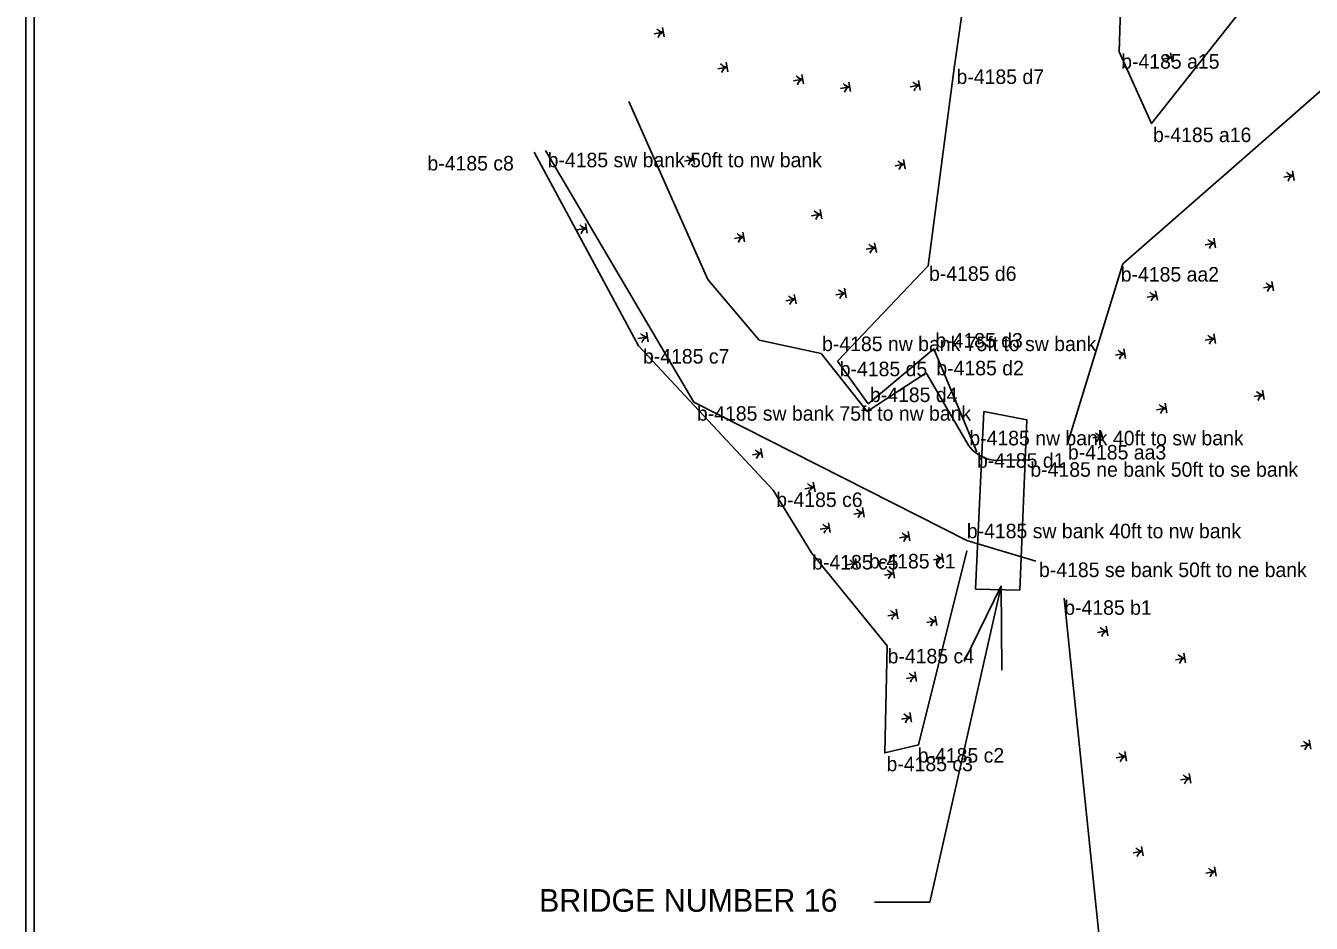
# Model space of a CAD drawing. Extents: x 2598976 to 2600165, y 728604 to 730243.
# Drawn here: x 2598981 to 2599645, y 729053 to 729516 of the extents above; entities that cross this region are included whole.
import ezdxf

# ---------------------------------------------------------------- set-up
doc = ezdxf.new("R2010")
doc.units = 0
for name, color, linetype in [('Old_Level_24', 7, 'Continuous'), ('Old_Level_3', 7, 'Continuous'), ('Old_Level_53', 7, 'Continuous'), ('Old_Level_57', 7, 'Continuous'), ('Old_Level_62', 7, 'Continuous'), ('Old_Level_63', 7, 'Continuous')]:
    doc.layers.add(name, color=color, linetype=linetype)

msp = doc.modelspace()

# ---------------------------------------------------------------- linework, layer by layer
at = {"layer": 'Old_Level_24'}
for q in [(2599465.37, 729187.6), (2599484.79, 729183.19)]:
    msp.add_line((2599484.45, 729226.71), q, dxfattribs=at)
msp.add_lwpolyline([(2599484.45, 729226.71), (2599447.49, 729063.45), (2599419.06, 729063.45)], dxfattribs=at)
at = {"layer": 'Old_Level_3'}
for p, q in [((2599545.29, 729502.48), (2599545.29, 729502.48)), ((2599460.2, 729494.04), (2599460.2, 729494.04)), ((2599562.01, 729465.34), (2599562.01, 729465.34)), ((2599243.27, 729450.6), (2599243.27, 729450.6)), ((2599249.09, 729451.44), (2599249.09, 729451.44)), ((2599446.79, 729391.93), (2599446.79, 729391.93)), ((2599547.27, 729393.05), (2599547.27, 729393.05)), ((2599297.2, 729350.67), (2599297.2, 729350.67)), ((2599391.39, 729346.71), (2599391.39, 729346.71)), ((2599449.61, 729349.02), (2599449.61, 729349.02)), ((2599399.91, 729342.76), (2599399.91, 729342.76)), ((2599445.74, 729336.77), (2599445.74, 729336.77)), ((2599449.86, 729334.51), (2599449.86, 729334.51)), ((2599325.74, 729321.49), (2599325.74, 729321.49)), ((2599415.76, 729320.71), (2599415.76, 729320.71)), ((2599467.76, 729298.97), (2599467.76, 729298.97)), ((2599518.57, 729299.5), (2599518.57, 729299.5)), ((2599471.85, 729295.85), (2599471.85, 729295.85)), ((2599498.93, 729291.63), (2599498.93, 729291.63)), ((2599366.72, 729276.06), (2599366.72, 729276.06)), ((2599466.66, 729244.73), (2599466.66, 729244.73)), ((2599466.74, 729250.08), (2599466.74, 729250.08)), ((2599386.45, 729243.82), (2599386.45, 729243.82)), ((2599502.33, 729239.52), (2599502.33, 729239.52)), ((2599471.16, 729225), (2599471.16, 729225)), ((2599494.08, 729224.45), (2599494.08, 729224.45)), ((2599516.89, 729220.46), (2599516.89, 729220.46)), ((2599425.63, 729195.77), (2599425.63, 729195.77)), ((2599441.76, 729144.65), (2599441.76, 729144.65)), ((2599424.26, 729140.46), (2599424.26, 729140.46))]:
    msp.add_line(p, q, dxfattribs=at)
at = {"layer": 'Old_Level_53'}
for p, q in [((2599249.09, 729451.44), (2599325.74, 729321.49)), ((2599445.74, 729336.77), (2599467.76, 729298.97)), ((2599325.74, 729321.49), (2599466.74, 729250.08)), ((2599485.95, 729291.74), (2599498.93, 729291.63)), ((2599498.93, 729291.63), (2599498.93, 729291.63)), ((2599502.33, 729239.52), (2599502.33, 729239.52))]:
    msp.add_line(p, q, dxfattribs=at)
for points in [[(2599292.16, 729476.85), (2599332.97, 729384.83), (2599359.49, 729353.63), (2599391.39, 729346.71)], [(2599391.39, 729346.71), (2599415.28, 729316.76), (2599445.74, 729336.77)], [(2599466.74, 729250.08), (2599502.33, 729239.52)]]:
    msp.add_lwpolyline(points, dxfattribs=at)
msp.add_arc((2599482.84, 729310.39), 18.91, 217.15364, 279.45884, dxfattribs=at)
at = {"layer": 'Old_Level_57'}
for p, q in [((2599309.95, 729512.54), (2599305.16, 729511.69)), ((2599310.39, 729510.08), (2599309.51, 729515)), ((2599343.26, 729492.07), (2599342.38, 729496.99)), ((2599572.36, 729499.5), (2599567.57, 729498.65)), ((2599572.8, 729497.04), (2599571.92, 729501.96)), ((2599342.82, 729494.53), (2599338.03, 729493.68)), ((2599382.39, 729485.81), (2599381.51, 729490.73)), ((2599381.95, 729488.27), (2599377.16, 729487.41)), ((2599406.21, 729484.35), (2599401.42, 729483.5)), ((2599406.65, 729481.89), (2599405.78, 729486.81)), ((2599442.21, 729485.14), (2599437.42, 729484.28)), ((2599442.65, 729482.67), (2599441.78, 729487.6)), ((2599325.6, 729446.77), (2599320.81, 729445.92)), ((2599326.04, 729444.31), (2599325.16, 729449.23)), ((2599434.39, 729444.42), (2599429.6, 729443.57)), ((2599434.83, 729441.96), (2599433.95, 729446.88)), ((2599635.24, 729438.53), (2599630.45, 729437.68)), ((2599635.68, 729436.07), (2599634.8, 729441)), ((2599391.34, 729418.58), (2599386.55, 729417.73)), ((2599391.78, 729416.12), (2599390.91, 729421.04)), ((2599270.19, 729411.32), (2599265.4, 729410.46)), ((2599270.63, 729408.86), (2599269.75, 729413.78)), ((2599351.43, 729406.84), (2599346.64, 729405.99)), ((2599351.87, 729404.38), (2599350.99, 729409.3)), ((2599419.96, 729398.9), (2599419.08, 729403.82)), ((2599594.61, 729403.7), (2599589.82, 729402.84)), ((2599595.05, 729401.23), (2599594.17, 729406.16)), ((2599419.52, 729401.36), (2599414.73, 729400.5)), ((2599625.03, 729378.98), (2599624.16, 729383.9)), ((2599378.48, 729372.28), (2599377.6, 729377.2)), ((2599403.87, 729377.87), (2599399.07, 729377.02)), ((2599404.3, 729375.41), (2599403.43, 729380.33)), ((2599565.06, 729374.14), (2599564.18, 729379.06)), ((2599624.6, 729381.44), (2599619.81, 729380.59)), ((2599378.04, 729374.74), (2599373.25, 729373.88)), ((2599564.62, 729376.6), (2599559.83, 729375.75)), ((2599302.07, 729352.73), (2599301.19, 729357.65)), ((2599301.63, 729355.19), (2599296.84, 729354.34)), ((2599594.61, 729354.34), (2599589.82, 729353.49)), ((2599595.05, 729351.88), (2599594.17, 729356.8)), ((2599548.18, 729346.6), (2599543.39, 729345.75)), ((2599548.62, 729344.14), (2599547.74, 729349.06)), ((2599619.76, 729325.31), (2599614.97, 729324.46)), ((2599620.2, 729322.85), (2599619.32, 729327.77)), ((2599569.46, 729318.54), (2599564.67, 729317.68)), ((2599569.9, 729316.07), (2599569.02, 729321)), ((2599536.57, 729304.02), (2599531.78, 729303.17)), ((2599537.01, 729301.56), (2599536.13, 729306.48)), ((2599361.19, 729292.78), (2599360.31, 729297.7)), ((2599360.75, 729295.24), (2599355.96, 729294.39)), ((2599387.84, 729277.75), (2599383.05, 729276.9)), ((2599388.28, 729275.29), (2599387.4, 729280.22)), ((2599413.19, 729264.64), (2599408.4, 729263.79)), ((2599413.63, 729262.18), (2599412.75, 729267.1)), ((2599396.15, 729254.31), (2599395.27, 729259.23)), ((2599395.71, 729256.77), (2599390.92, 729255.92)), ((2599436.78, 729252.4), (2599431.99, 729251.55)), ((2599437.22, 729249.94), (2599436.35, 729254.86)), ((2599409.69, 729238.41), (2599404.9, 729237.56)), ((2599410.13, 729235.95), (2599409.25, 729240.87)), ((2599454.26, 729241.03), (2599449.47, 729240.18)), ((2599454.7, 729238.57), (2599453.82, 729243.49)), ((2599428.92, 729233.17), (2599424.13, 729232.31)), ((2599429.36, 729230.7), (2599428.48, 729235.63)), ((2599430.67, 729212.18), (2599425.88, 729211.33)), ((2599431.1, 729209.72), (2599430.23, 729214.64)), ((2599451.2, 729206.22), (2599450.33, 729211.15)), ((2599450.77, 729208.68), (2599445.98, 729207.83)), ((2599539.47, 729200.98), (2599538.6, 729205.9)), ((2599539.03, 729203.44), (2599534.24, 729202.59)), ((2599579.67, 729186.99), (2599578.8, 729191.91)), ((2599579.23, 729189.45), (2599574.44, 729188.6)), ((2599440.28, 729179.83), (2599435.49, 729178.98)), ((2599440.72, 729177.37), (2599439.84, 729182.29)), ((2599437.66, 729158.85), (2599432.87, 729158)), ((2599438.1, 729156.39), (2599437.22, 729161.31)), ((2599643.91, 729144.86), (2599639.12, 729144.01)), ((2599644.34, 729142.4), (2599643.47, 729147.32)), ((2599548.65, 729138.74), (2599543.86, 729137.89)), ((2599549.09, 729136.28), (2599548.21, 729141.2)), ((2599581.86, 729127.37), (2599577.07, 729126.52)), ((2599582.29, 729124.91), (2599581.42, 729129.84)), ((2599557.82, 729087.32), (2599556.95, 729092.24)), ((2599557.39, 729089.78), (2599552.6, 729088.93)), ((2599594.97, 729079.29), (2599590.17, 729078.43)), ((2599595.4, 729076.83), (2599594.53, 729081.75))]:
    msp.add_line(p, q, dxfattribs=at)
for points in [[(2599764.34, 729950.8), (2599742.64, 729983.6), (2599681.7, 730025.47), (2599631.03, 730026.43), (2599593.82, 730004.86), (2599608.29, 729947.7), (2599585.75, 729914.54), (2599653.16, 729873.76), (2599674.31, 729743.3), (2599629.44, 729763.19), (2599658.53, 729696.04), (2599576.74, 729699.88), (2599550.79, 729678.88), (2599545.29, 729502.48), (2599562.01, 729465.34), (2599616.95, 729534.95), (2599677.31, 729603.47), (2599722.5, 729643.95), (2599752.22, 729664.15), (2599754.67, 729686.08), (2599736.31, 729726.61), (2599721.7, 729811.02), (2599739.87, 729881.74), (2599761.65, 729918)], [(2599471.85, 729295.85), (2599449.61, 729349.02), (2599415.76, 729320.71), (2599399.91, 729342.76), (2599446.79, 729391.93), (2599460.2, 729494.04), (2599469.1, 729556.89), (2599490.39, 729587.95), (2599477.33, 729671.46), (2599443.13, 729793.12), (2599371.81, 729729.07), (2599251, 729735.76)], [(2599681.53, 729510.24), (2599547.27, 729393.05), (2599518.57, 729299.5)], [(2599466.66, 729244.73), (2599441.76, 729144.65), (2599424.26, 729140.46), (2599425.63, 729195.77), (2599386.45, 729243.82), (2599366.72, 729276.06), (2599297.2, 729350.67), (2599243.27, 729450.6)], [(2599516.89, 729220.46), (2599540.31, 728994.01), (2599562.39, 728942.84), (2599631.97, 728932.34), (2599687.87, 728961.4), (2599745.82, 728966.7)]]:
    msp.add_lwpolyline(points, dxfattribs=at)
for centre, radius, start, end in [((2599310.42, 729517.67), 5.15, 220.90031, 264.24799), ((2599311, 729508.79), 3.87, 105.65345, 165.99432), ((2599572.83, 729504.64), 5.15, 220.90031, 264.24799), ((2599573.41, 729495.75), 3.87, 105.65345, 165.99432), ((2599343.29, 729499.66), 5.15, 220.90031, 264.24799), ((2599343.87, 729490.78), 3.87, 105.65345, 165.99432), ((2599382.42, 729493.4), 5.15, 220.90031, 264.24799), ((2599383, 729484.51), 3.87, 105.65345, 165.99432), ((2599406.68, 729489.49), 5.15, 220.90031, 264.24799), ((2599407.26, 729480.6), 3.87, 105.65345, 165.99432), ((2599442.68, 729490.27), 5.15, 220.90031, 264.24799), ((2599443.26, 729481.38), 3.87, 105.65345, 165.99432), ((2599326.07, 729451.9), 5.15, 220.90031, 264.24799), ((2599326.65, 729443.02), 3.87, 105.65345, 165.99432), ((2599434.86, 729449.56), 5.15, 220.90031, 264.24799), ((2599435.44, 729440.67), 3.87, 105.65345, 165.99432), ((2599635.7, 729443.67), 5.15, 220.90031, 264.24799), ((2599636.29, 729434.78), 3.87, 105.65345, 165.99432), ((2599391.81, 729423.72), 5.15, 220.90031, 264.24799), ((2599392.39, 729414.83), 3.87, 105.65345, 165.99432), ((2599270.66, 729416.45), 5.15, 220.90031, 264.24799), ((2599271.24, 729407.56), 3.87, 105.65345, 165.99432), ((2599351.9, 729411.97), 5.15, 220.90031, 264.24799), ((2599352.48, 729403.09), 3.87, 105.65345, 165.99432), ((2599595.08, 729408.83), 5.15, 220.90031, 264.24799), ((2599595.66, 729399.94), 3.87, 105.65345, 165.99432), ((2599419.99, 729406.49), 5.15, 220.90031, 264.24799), ((2599420.57, 729397.61), 3.87, 105.65345, 165.99432), ((2599404.33, 729383), 5.15, 220.90031, 264.24799), ((2599404.91, 729374.12), 3.87, 105.65345, 165.99432), ((2599565.09, 729381.73), 5.15, 220.90031, 264.24799), ((2599625.06, 729386.57), 5.15, 220.90031, 264.24799), ((2599625.64, 729377.69), 3.87, 105.65345, 165.99432), ((2599378.51, 729379.87), 5.15, 220.90031, 264.24799), ((2599379.09, 729370.98), 3.87, 105.65345, 165.99432), ((2599565.67, 729372.85), 3.87, 105.65345, 165.99432), ((2599302.1, 729360.32), 5.15, 220.90031, 264.24799), ((2599302.68, 729351.44), 3.87, 105.65345, 165.99432), ((2599595.08, 729359.48), 5.15, 220.90031, 264.24799), ((2599595.66, 729350.59), 3.87, 105.65345, 165.99432), ((2599548.64, 729351.73), 5.15, 220.90031, 264.24799), ((2599549.23, 729342.85), 3.87, 105.65345, 165.99432), ((2599620.23, 729330.44), 5.15, 220.90031, 264.24799), ((2599620.81, 729321.56), 3.87, 105.65345, 165.99432), ((2599569.93, 729323.67), 5.15, 220.90031, 264.24799), ((2599570.51, 729314.78), 3.87, 105.65345, 165.99432), ((2599537.04, 729309.15), 5.15, 220.90031, 264.24799), ((2599537.62, 729300.27), 3.87, 105.65345, 165.99432), ((2599361.22, 729300.37), 5.15, 220.90031, 264.24799), ((2599361.8, 729291.49), 3.87, 105.65345, 165.99432), ((2599388.31, 729282.89), 5.15, 220.90031, 264.24799), ((2599388.89, 729274), 3.87, 105.65345, 165.99432), ((2599413.65, 729269.77), 5.15, 220.90031, 264.24799), ((2599414.24, 729260.89), 3.87, 105.65345, 165.99432), ((2599396.18, 729261.91), 5.15, 220.90031, 264.24799), ((2599396.76, 729253.02), 3.87, 105.65345, 165.99432), ((2599437.25, 729257.53), 5.15, 220.90031, 264.24799), ((2599437.83, 729248.65), 3.87, 105.65345, 165.99432), ((2599410.16, 729243.55), 5.15, 220.90031, 264.24799), ((2599410.74, 729234.66), 3.87, 105.65345, 165.99432), ((2599454.73, 729246.17), 5.15, 220.90031, 264.24799), ((2599455.31, 729237.28), 3.87, 105.65345, 165.99432), ((2599429.39, 729238.3), 5.15, 220.90031, 264.24799), ((2599429.97, 729229.41), 3.87, 105.65345, 165.99432), ((2599431.13, 729217.32), 5.15, 220.90031, 264.24799), ((2599431.71, 729208.43), 3.87, 105.65345, 165.99432), ((2599451.23, 729213.82), 5.15, 220.90031, 264.24799), ((2599451.81, 729204.93), 3.87, 105.65345, 165.99432), ((2599539.5, 729208.57), 5.15, 220.90031, 264.24799), ((2599540.08, 729199.69), 3.87, 105.65345, 165.99432), ((2599579.7, 729194.58), 5.15, 220.90031, 264.24799), ((2599580.28, 729185.7), 3.87, 105.65345, 165.99432), ((2599440.75, 729184.97), 5.15, 220.90031, 264.24799), ((2599441.33, 729176.08), 3.87, 105.65345, 165.99432), ((2599438.12, 729163.98), 5.15, 220.90031, 264.24799), ((2599438.71, 729155.1), 3.87, 105.65345, 165.99432), ((2599644.37, 729149.99), 5.15, 220.90031, 264.24799), ((2599644.95, 729141.11), 3.87, 105.65345, 165.99432), ((2599549.11, 729143.87), 5.15, 220.90031, 264.24799), ((2599549.69, 729134.99), 3.87, 105.65345, 165.99432), ((2599582.32, 729132.51), 5.15, 220.90031, 264.24799), ((2599582.9, 729123.62), 3.87, 105.65345, 165.99432), ((2599557.85, 729094.91), 5.15, 220.90031, 264.24799), ((2599558.43, 729086.03), 3.87, 105.65345, 165.99432), ((2599595.43, 729084.42), 5.15, 220.90031, 264.24799), ((2599596.01, 729075.54), 3.87, 105.65345, 165.99432)]:
    msp.add_arc(centre, radius, start, end, dxfattribs=at)
at = {"layer": 'Old_Level_62'}
for p, q in [((2599471.16, 729225), (2599475.49, 729316.75)), ((2599475.49, 729316.75), (2599497.58, 729312.52)), ((2599497.58, 729312.52), (2599494.08, 729224.45)), ((2599494.08, 729224.45), (2599471.16, 729225))]:
    msp.add_line(p, q, dxfattribs=at)
at = {"layer": 'Old_Level_63'}
for p, q in [((2598980.71, 728675.66), (2598980.71, 730208.07)), ((2598980.71, 728675.66), (2598980.71, 730208.07)), ((2598980.71, 728675.66), (2598980.71, 730208.07)), ((2598985.01, 728674.53), (2598985.01, 730208.54)), ((2598985.01, 728674.53), (2598985.01, 730208.54)), ((2598985.01, 728674.53), (2598985.01, 730208.54))]:
    msp.add_line(p, q, dxfattribs=at)

# ---------------------------------------------------------------- texts
at = {"layer": 'Old_Level_24'}
for s, height, p in [('b-4185 a15', 7.5, (2599546.39, 729493.7)), ('b-4185 d7', 7.5, (2599461.37, 729485.81)), ('b-4185 a16', 7.5, (2599562.84, 729455.8)), ('b-4185 sw bank 50ft to nw bank', 7.5, (2599250.22, 729442.82)), ('b-4185 c8', 7.5, (2599188.16, 729441.15)), ('b-4185 d6', 7.5, (2599447.16, 729384.16)), ('b-4185 aa2', 7.5, (2599546.15, 729383.81)), ('b-4185 d3', 7.5, (2599450.41, 729349.71)), ('b-4185 nw bank 75ft to sw bank', 7.5, (2599391.93, 729347.91)), ('b-4185 c7', 7.5, (2599299.45, 729341.49)), ('b-4185 d5', 7.5, (2599401.05, 729334.95)), ('b-4185 d2', 7.5, (2599450.95, 729335.41)), ('b-4185 d4', 7.5, (2599416.66, 729321.61)), ('b-4185 sw bank 75ft to nw bank', 7.5, (2599327.31, 729311.99)), ('b-4185 nw bank 40ft to sw bank', 7.5, (2599467.98, 729299.26)), ('b-4185 aa3', 7.5, (2599518.88, 729291.95)), ('b-4185 d1', 7.5, (2599471.91, 729287.72)), ('b-4185 ne bank 50ft to se bank', 7.5, (2599499.5, 729283.04)), ('b-4185 c6', 7.5, (2599368.25, 729267.45)), ('b-4185 sw bank 40ft to nw bank', 7.5, (2599466.69, 729251.31)), ('b-4185 c5', 7.5, (2599386.82, 729235.16)), ('b-4185 c1', 7.5, (2599416.21, 729235.72)), ('b-4185 se bank 50ft to ne bank', 7.5, (2599503.95, 729231.26)), ('b-4185 b1', 7.5, (2599516.99, 729211.78)), ('b-4185 c4', 7.5, (2599425.77, 729186.72)), ('b-4185 c3', 7.5, (2599425.22, 729131.05)), ('b-4185 c2', 7.5, (2599441.35, 729135.51)), ('BRIDGE NUMBER 16', 11.7188, (2599245.77, 729058.49))]:
    msp.add_text(s, height=height, dxfattribs=at).set_placement(p)

doc.saveas('drawing.dxf')
